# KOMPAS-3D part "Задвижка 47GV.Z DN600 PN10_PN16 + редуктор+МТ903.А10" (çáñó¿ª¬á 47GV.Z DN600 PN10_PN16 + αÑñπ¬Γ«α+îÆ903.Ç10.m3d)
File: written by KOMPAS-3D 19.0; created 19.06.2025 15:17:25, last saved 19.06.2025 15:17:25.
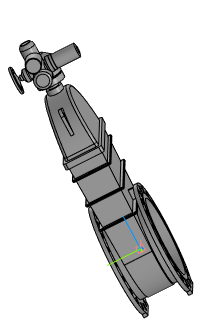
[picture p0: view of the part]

Document properties: Полное имя файла: Задвижка 47GV.Z DN600 PN10_PN16 + редуктор+МТ903.А10.a3d

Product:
- Part/product: Задвижка 47GV.Z DN600 PN10_PN16 + редуктор+МТ903.А10
    Масса: 1855.28

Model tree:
1. Операция без истории:1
